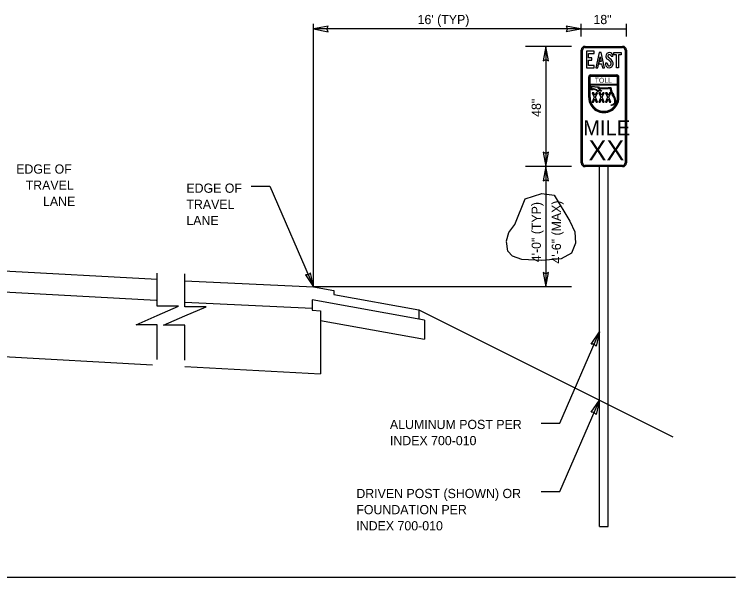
# Model space of a CAD drawing. Extents: x 56768 to 57406, y 11696 to 12105.
# Drawn here: x 57187.3 to 57405.9, y 11934.3 to 12105.2 of the extents above; entities that cross this region are included whole.
import ezdxf

# ---------------------------------------------------------------- set-up
doc = ezdxf.new("R2010")
doc.units = 0
for name, color, linetype in [('1', 7, 'Continuous'), ('52', 7, 'Continuous'), ('62', 7, 'Continuous'), ('Default', 7, 'Continuous'), ('DimLines_dp', 7, 'Continuous'), ('SheetBorder_dp', 7, 'Continuous'), ('SignPanel', 7, 'Continuous'), ('XSGrdLine_ex', 7, 'Continuous')]:
    doc.layers.add(name, color=color, linetype=linetype)

msp = doc.modelspace()

# ---------------------------------------------------------------- linework, layer by layer
at = {"layer": '1'}
for p, q in [((57364.62, 11988.09), (57364.62, 12058.97)), ((57367.28, 11986.75), (57367.28, 12058.97)), ((57364.62, 11949.76), (57364.62, 11988.09)), ((57367.28, 11949.76), (57367.28, 11986.75)), ((57364.62, 11949.76), (57367.28, 11949.76))]:
    msp.add_line(p, q, dxfattribs=at)
at = {"layer": '52'}
msp.add_line((57356.11, 12022.47), (57277.99, 12022.47), dxfattribs=at)
at = {"layer": '62'}
msp.add_lwpolyline([(57336.45, 12036.41), (57337.15, 12039.01), (57338.95, 12041.42), (57342.06, 12049.17), (57347.16, 12050.77), (57350.86, 12050.27), (57355.66, 12042.42), (57357.16, 12039.21), (57357.36, 12035.71), (57356.16, 12032.7), (57353.06, 12031), (57347.16, 12030.5), (57341.05, 12030.8), (57338.25, 12031.8), (57336.85, 12033.31), (57336.45, 12036.21)], dxfattribs=at)
at = {"layer": 'Default'}
for points in [[(57230.6, 12000.41), (57230.6, 12010.97), (57224.14, 12010.97), (57230.6, 12013.79), (57237.06, 12016.6), (57230.6, 12016.6), (57230.6, 12026.6)], [(57238.9, 12000.28), (57238.9, 12010.84), (57232.44, 12010.84), (57238.9, 12013.65), (57245.36, 12016.47), (57238.9, 12016.47), (57238.9, 12026.47)]]:
    msp.add_lwpolyline(points, dxfattribs=at)
at = {"layer": 'DimLines_dp'}
for p, q in [((57277.99, 12022.47), (57277.99, 12102.3)), ((57359.11, 12098.47), (57359.11, 12102.3)), ((57372.79, 12098.47), (57372.79, 12102.3)), ((57282.34, 12101.56), (57277.99, 12100.75)), ((57359.11, 12100.75), (57277.99, 12100.75)), ((57277.99, 12100.75), (57282.34, 12099.91)), ((57282.01, 12100.75), (57282.34, 12101.56)), ((57282.34, 12099.91), (57282.01, 12100.75)), ((57358.92, 12100.75), (57354.57, 12101.59)), ((57354.57, 12101.59), (57354.9, 12100.75)), ((57354.9, 12100.75), (57354.57, 12099.94)), ((57354.57, 12099.94), (57358.92, 12100.75)), ((57359.11, 12100.75), (57372.79, 12100.75)), ((57356.11, 12095.47), (57342.18, 12095.47)), ((57348.36, 12095.47), (57347.52, 12091.12)), ((57348.36, 12095.47), (57348.36, 12058.97)), ((57349.17, 12091.12), (57348.36, 12095.47)), ((57347.52, 12091.12), (57348.36, 12091.45)), ((57348.36, 12091.45), (57349.17, 12091.12)), ((57348.36, 12062.99), (57347.55, 12063.32)), ((57347.55, 12063.32), (57348.36, 12058.97)), ((57348.36, 12062.99), (57347.55, 12063.32)), ((57347.55, 12063.32), (57348.36, 12058.97)), ((57348.36, 12058.97), (57349.2, 12063.32)), ((57349.2, 12063.32), (57348.36, 12062.99)), ((57348.36, 12058.97), (57349.2, 12063.32)), ((57349.2, 12063.32), (57348.36, 12062.99)), ((57356.11, 12058.97), (57342.18, 12058.97)), ((57348.36, 12058.97), (57347.52, 12054.62)), ((57348.36, 12058.97), (57348.36, 12022.47)), ((57349.17, 12054.62), (57348.36, 12058.97)), ((57347.52, 12054.62), (57348.36, 12054.95)), ((57348.36, 12054.95), (57349.17, 12054.62)), ((57259.02, 12053.08), (57264.67, 12053.08)), ((57264.67, 12053.08), (57277.99, 12022.46)), ((57276.38, 12026.15), (57275.51, 12026.13)), ((57275.51, 12026.13), (57277.99, 12022.46)), ((57277.02, 12026.79), (57276.38, 12026.15)), ((57277.99, 12022.46), (57277.02, 12026.79)), ((57348.36, 12026.49), (57347.55, 12026.82)), ((57347.55, 12026.82), (57348.36, 12022.47)), ((57348.36, 12022.47), (57349.2, 12026.82)), ((57349.2, 12026.82), (57348.36, 12026.49)), ((57352.58, 11981.13), (57364.62, 12008.81)), ((57362.14, 12005.14), (57364.62, 12008.81)), ((57364.62, 12008.81), (57363.65, 12004.48)), ((57363.01, 12005.12), (57362.14, 12005.14)), ((57363.65, 12004.48), (57363.01, 12005.12)), ((57352.58, 11960.41), (57364.62, 11988.09)), ((57362.14, 11984.42), (57364.62, 11988.09)), ((57364.62, 11988.09), (57363.65, 11983.76)), ((57363.01, 11984.4), (57362.14, 11984.42)), ((57363.65, 11983.76), (57363.01, 11984.4)), ((57346.93, 11981.13), (57352.58, 11981.13)), ((57346.93, 11960.41), (57352.58, 11960.41))]:
    msp.add_line(p, q, dxfattribs=at)
at = {"layer": 'SheetBorder_dp'}
msp.add_line((57405.89, 11934.25), (56789.89, 11934.25), dxfattribs=at)
at = {"layer": 'SignPanel'}
for p, q in [((57368.14, 12092.46), (57368.73, 12092.46)), ((57368.14, 12092.46), (57368.73, 12092.46)), ((57368.14, 12092.46), (57368.73, 12092.46)), ((57367.01, 12090.42), (57366.41, 12090.42)), ((57367.01, 12090.42), (57366.41, 12090.42)), ((57367.01, 12090.42), (57366.41, 12090.42)), ((57361.96, 12086.8), (57369.94, 12086.8)), ((57361.39, 12079.95), (57361.39, 12086.23)), ((57361.58, 12079.95), (57361.58, 12086.23)), ((57361.77, 12083.95), (57361.77, 12086.23)), ((57361.96, 12086.61), (57369.94, 12086.61)), ((57361.96, 12086.42), (57369.94, 12086.42)), ((57370.13, 12083.95), (57370.13, 12086.23)), ((57370.32, 12079.95), (57370.32, 12086.23)), ((57370.51, 12079.95), (57370.51, 12086.23)), ((57361.77, 12083.95), (57370.13, 12083.95)), ((57361.77, 12079.95), (57361.77, 12083.76)), ((57361.77, 12083.76), (57370.13, 12083.76)), ((57362.15, 12082.3), (57361.98, 12083.39)), ((57361.98, 12083.39), (57364.36, 12083.21)), ((57364.2, 12082.99), (57362.25, 12083.14)), ((57362.25, 12083.14), (57362.35, 12082.51)), ((57362.35, 12082.51), (57362.54, 12082.48)), ((57362.54, 12082.48), (57362.81, 12082.7)), ((57362.86, 12082.44), (57362.61, 12082.24)), ((57362.81, 12082.7), (57363.73, 12082.4)), ((57363.61, 12082.19), (57362.86, 12082.44)), ((57363.24, 12083.05), (57363.24, 12083.05)), ((57363.73, 12082.4), (57364.18, 12081.98)), ((57364.34, 12082.63), (57364.2, 12082.99)), ((57367.35, 12082.63), (57364.34, 12082.63)), ((57364.36, 12083.21), (57364.5, 12082.86)), ((57364.5, 12082.86), (57367.23, 12082.86)), ((57367.23, 12082.86), (57367.33, 12083.02)), ((57367.33, 12083.02), (57368.06, 12083.02)), ((57367.45, 12082.79), (57367.35, 12082.63)), ((57367.88, 12082.79), (57367.45, 12082.79)), ((57368.18, 12081.5), (57367.88, 12082.79)), ((57368.06, 12083.02), (57368.4, 12081.58)), ((57370.13, 12079.95), (57370.13, 12083.76)), ((57362.61, 12082.24), (57362.15, 12082.3)), ((57364.15, 12081.7), (57363.61, 12082.19)), ((57364.78, 12082.07), (57364.15, 12081.7)), ((57364.18, 12081.98), (57364.79, 12082.34)), ((57365.16, 12081.81), (57364.78, 12082.07)), ((57364.79, 12082.34), (57365.29, 12082)), ((57365.29, 12082), (57365.16, 12081.81)), ((57368.62, 12080.79), (57368.18, 12081.5)), ((57368.4, 12081.58), (57368.85, 12080.86)), ((57368.62, 12080.61), (57368.62, 12080.79)), ((57369.05, 12079.91), (57368.62, 12080.61)), ((57368.85, 12080.86), (57368.85, 12080.67)), ((57368.85, 12080.67), (57369.26, 12080)), ((57368.65, 12077.81), (57369.28, 12078.32)), ((57369.51, 12078.21), (57368.76, 12077.6)), ((57369.28, 12079.05), (57369.05, 12079.91)), ((57369.26, 12080), (57369.51, 12079.08)), ((57369.28, 12078.32), (57369.28, 12079.05)), ((57369.51, 12079.08), (57369.51, 12078.21)), ((57368.18, 12077.67), (57368.31, 12077.86)), ((57368.4, 12077.51), (57368.18, 12077.67)), ((57368.31, 12077.86), (57368.45, 12077.76)), ((57368.76, 12077.6), (57368.4, 12077.51)), ((57368.45, 12077.76), (57368.65, 12077.81))]:
    msp.add_line(p, q, dxfattribs=at)
for points in [[(57360.25, 12095.47), (57371.65, 12095.47)], [(57359.11, 12060.11), (57359.11, 12094.33)], [(57359.49, 12060.11), (57359.49, 12094.33)], [(57360.25, 12095.09), (57371.65, 12095.09)], [(57372.41, 12094.33), (57372.41, 12060.11)], [(57372.79, 12094.33), (57372.79, 12060.11)], [(57371.65, 12059.35), (57360.25, 12059.35)], [(57371.65, 12058.97), (57360.25, 12058.97)]]:
    msp.add_lwpolyline(points, dxfattribs=at)
for points in [[(57361.31, 12089.69), (57361.31, 12091.31), (57362.33, 12091.31), (57362.33, 12092.02), (57361.31, 12092.02), (57361.31, 12093.34), (57363.03, 12093.34), (57363.03, 12094.05), (57360.66, 12094.05), (57360.66, 12088.98), (57363.03, 12088.98), (57363.03, 12089.69)], [(57361.31, 12089.69), (57361.31, 12091.31), (57362.33, 12091.31), (57362.33, 12092.02), (57361.31, 12092.02), (57361.31, 12093.34), (57363.03, 12093.34), (57363.03, 12094.05), (57360.66, 12094.05), (57360.66, 12088.98), (57363.03, 12088.98), (57363.03, 12089.69)], [(57361.31, 12089.69), (57361.31, 12091.31), (57362.33, 12091.31), (57362.33, 12092.02), (57361.31, 12092.02), (57361.31, 12093.34), (57363.03, 12093.34), (57363.03, 12094.05), (57360.66, 12094.05), (57360.66, 12088.98), (57363.03, 12088.98), (57363.03, 12089.69)], [(57365.28, 12090.21), (57365.55, 12088.98), (57366.16, 12088.98), (57365.14, 12093.56), (57364.51, 12093.56), (57363.49, 12088.98), (57364.09, 12088.98), (57364.37, 12090.21)], [(57364.51, 12090.85), (57364.37, 12090.21), (57365.28, 12090.21), (57365.55, 12088.98), (57366.16, 12088.98), (57365.14, 12093.56), (57364.51, 12093.56), (57363.49, 12088.98), (57364.09, 12088.98), (57364.82, 12092.26), (57365.14, 12090.85)], [(57364.51, 12090.85), (57364.37, 12090.21), (57365.28, 12090.21), (57365.55, 12088.98), (57366.16, 12088.98), (57365.14, 12093.56), (57364.51, 12093.56), (57363.49, 12088.98), (57364.09, 12088.98), (57364.82, 12092.26), (57365.14, 12090.85)], [(57369.79, 12092.92), (57369.01, 12092.92), (57369.01, 12093.56), (57371.16, 12093.56), (57371.16, 12092.92), (57370.38, 12092.92), (57370.38, 12088.98), (57369.79, 12088.98)], [(57369.79, 12092.92), (57369.01, 12092.92), (57369.01, 12093.56), (57371.16, 12093.56), (57371.16, 12092.92), (57370.38, 12092.92), (57370.38, 12088.98), (57369.79, 12088.98)], [(57369.79, 12092.92), (57369.01, 12092.92), (57369.01, 12093.56), (57371.16, 12093.56), (57371.16, 12092.92), (57370.38, 12092.92), (57370.38, 12088.98), (57369.79, 12088.98)], [(57364.82, 12092.26), (57365.14, 12090.85), (57364.51, 12090.85)], [(57362.84, 12078.53), (57363.25, 12079.51), (57363.66, 12078.53), (57364.08, 12078.53), (57363.46, 12080.02), (57364.03, 12081.39), (57363.61, 12081.39), (57363.25, 12080.53), (57362.89, 12081.39), (57362.46, 12081.39), (57363.03, 12080.02), (57362.41, 12078.53)], [(57364.86, 12078.53), (57365.26, 12079.51), (57365.67, 12078.53), (57366.1, 12078.53), (57365.48, 12080.02), (57366.05, 12081.39), (57365.62, 12081.39), (57365.26, 12080.53), (57364.91, 12081.39), (57364.48, 12081.39), (57365.05, 12080.02), (57364.43, 12078.53)], [(57366.87, 12078.53), (57367.28, 12079.51), (57367.69, 12078.53), (57368.12, 12078.53), (57367.49, 12080.02), (57368.07, 12081.39), (57367.64, 12081.39), (57367.28, 12080.53), (57366.92, 12081.39), (57366.49, 12081.39), (57367.07, 12080.02), (57366.44, 12078.53)]]:
    msp.add_lwpolyline(points, close=True, dxfattribs=at)
for centre, radius, start, end in [((57360.25, 12094.33), 1.14, 90, 180), ((57371.65, 12094.33), 1.14, 0, 90), ((57360.25, 12094.33), 0.76, 90, 180), ((57371.65, 12094.33), 0.76, 0, 90), ((57360.25, 12060.11), 1.14, 180, 270), ((57360.25, 12060.11), 0.76, 180, 270), ((57371.65, 12060.11), 1.14, 270, 360), ((57371.65, 12060.11), 0.76, 270, 360)]:
    msp.add_arc(centre, radius, start, end, dxfattribs=at)
for centre, major_axis, ratio, start_param, end_param in [((57367.64, 12092.43), (0, 1.19), 0.91923, 4.736267, 7.790596), ((57367.64, 12092.43), (0, 1.19), 0.91923, 4.736267, 7.790596), ((57367.64, 12092.43), (0, 1.19), 0.91923, 4.736267, 7.790596), ((57367.53, 12092.47), (0, 1.07), 0.91923, 1.534831, 2.511766), ((57367.53, 12092.47), (0, 1.07), 0.91923, 1.534831, 2.511766), ((57367.53, 12092.47), (0, 1.07), 0.91923, 1.534831, 2.511766), ((57364.92, 12087.53), (0, 4.63), 0.91923, 5.515137, 5.786988), ((57364.92, 12087.53), (0, 4.63), 0.91923, 5.515137, 5.786988), ((57364.92, 12087.53), (0, 4.63), 0.91923, 5.515137, 5.786988), ((57367.57, 12092.49), (0, 0.46), 0.91923, 0.87378, 2.656959), ((57367.57, 12092.49), (0, 0.46), 0.91923, 0.87378, 2.656959), ((57367.57, 12092.49), (0, 0.46), 0.91923, 0.87378, 2.656959), ((57367.63, 12092.42), (0, 0.558), 0.91923, 4.786904, 7.140738), ((57367.63, 12092.42), (0, 0.558), 0.91923, 4.786904, 7.140738), ((57367.63, 12092.42), (0, 0.558), 0.91923, 4.786904, 7.140738), ((57365.43, 12088.23), (0, 4.39), 0.91923, 5.462886, 5.782242), ((57365.43, 12088.23), (0, 4.39), 0.91923, 5.462886, 5.782242), ((57365.43, 12088.23), (0, 4.39), 0.91923, 5.462886, 5.782242), ((57367.45, 12090.23), (0, 1.42), 0.91923, 4.260987, 5.485755), ((57367.45, 12090.23), (0, 1.42), 0.91923, 4.260987, 5.485755), ((57367.45, 12090.23), (0, 1.42), 0.91923, 4.260987, 5.485755), ((57367.79, 12090.35), (0, 1.5), 0.91923, 1.526364, 2.701682), ((57367.79, 12090.35), (0, 1.5), 0.91923, 1.526364, 2.701682), ((57367.79, 12090.35), (0, 1.5), 0.91923, 1.526364, 2.701682), ((57367.84, 12090.38), (0, 0.911), 0.91923, 1.524757, 2.28214), ((57367.84, 12090.38), (0, 0.911), 0.91923, 1.524757, 2.28214), ((57367.84, 12090.38), (0, 0.911), 0.91923, 1.524757, 2.28214), ((57367.6, 12090.17), (0, 1.24), 0.91923, 2.786047, 4.251692), ((57367.6, 12090.17), (0, 1.24), 0.91923, 2.786047, 4.251692), ((57367.6, 12090.17), (0, 1.24), 0.91923, 2.786047, 4.251692), ((57367.62, 12090.15), (0, 0.581), 0.91923, 2.261787, 4.23006), ((57367.62, 12090.15), (0, 0.581), 0.91923, 2.261787, 4.23006), ((57367.62, 12090.15), (0, 0.581), 0.91923, 2.261787, 4.23006), ((57367.44, 12090.23), (0, 0.792), 0.91923, 4.254409, 5.632398), ((57367.44, 12090.23), (0, 0.792), 0.91923, 4.254409, 5.632398), ((57367.44, 12090.23), (0, 0.792), 0.91923, 4.254409, 5.632398), ((57361.96, 12086.23), (0, 0.57), 0.9997, 0, 1.570796), ((57369.94, 12086.23), (0, 0.57), 0.9997, 4.712389, 6.283185), ((57361.96, 12086.23), (0, 0.38), 0.9997, 0, 1.570796), ((57361.96, 12086.23), (0, 0.19), 0.9997, 0, 1.570796), ((57369.94, 12086.23), (0, 0.38), 0.9997, 4.712389, 6.283185), ((57369.94, 12086.23), (0, 0.19), 0.9997, 4.712389, 6.283185), ((57365.95, 12079.95), (0, -4.56), 0.9997, 4.712389, 7.853982), ((57365.95, 12079.95), (0, -4.37), 0.9997, 4.712389, 7.853982), ((57365.95, 12079.95), (0, -4.18), 0.9997, 4.712389, 7.853982)]:
    msp.add_ellipse(centre, major_axis=major_axis, ratio=ratio, start_param=start_param, end_param=end_param, dxfattribs=at)
at = {"layer": 'XSGrdLine_ex'}
for p, q in [((57167.72, 12028.26), (57230.6, 12024.78)), ((57230.24, 12018.3), (57168, 12021.75)), ((57277.99, 12022.46), (57284.15, 12021.36)), ((57284.15, 12021.36), (57284.15, 12020.18)), ((57284.15, 12020.18), (57309.87, 12015.55)), ((57277.57, 12018.53), (57277.57, 12015.37)), ((57311.57, 12012.41), (57277.57, 12018.53)), ((57277.57, 12015.37), (57280.04, 12015.22)), ((57280.04, 12015.22), (57280.04, 11996.05)), ((57309.87, 12015.55), (57309.87, 12012.71)), ((57311.57, 12012.41), (57311.57, 12006.59)), ((57280.04, 12012.26), (57311.57, 12006.59)), ((57167.12, 12002.3), (57229.16, 11998.86)), ((57238.9, 11998.32), (57280.04, 11996.05))]:
    msp.add_line(p, q, dxfattribs=at)
for points in [[(57238.9, 12024.32), (57277.99, 12022.46)], [(57238.9, 12017.82), (57277.57, 12015.99)], [(57309.87, 12015.55), (57386.82, 11976.95)]]:
    msp.add_lwpolyline(points, dxfattribs=at)

# ---------------------------------------------------------------- texts
at = {"layer": 'DimLines_dp'}
for s, p in [("16' (TYP)", (57309.5, 12102.22)), ('18"', (57362.81, 12102.22)), ('EDGE OF ', (57187.82, 12056.84)), ('TRAVEL ', (57190.69, 12051.94)), ('EDGE OF ', (57239.41, 12051.04)), ('LANE', (57195.95, 12047.04)), ('TRAVEL ', (57239.41, 12046.14)), ('LANE', (57239.41, 12041.24)), ('ALUMINUM POST PER', (57301.11, 11979.33)), ('INDEX 700-010', (57301.11, 11974.43)), ('DRIVEN POST (SHOWN) OR', (57290.93, 11958.38)), ('FOUNDATION PER', (57290.93, 11953.48)), ('INDEX 700-010', (57290.93, 11948.58))]:
    msp.add_text(s, height=2.8, dxfattribs=at).set_placement(p)
for s, p in [('48"', (57346.87, 12074.08)), ('4\'-0" (TYP)', (57346.87, 12029.97)), ('4\'-6" (MAX)', (57352.95, 12029.57))]:
    msp.add_text(s, height=2.8, rotation=90, dxfattribs=at).set_placement(p)
at = {"layer": 'SignPanel'}
for s, height, p in [('TOLL', 1.519, (57363.19, 12084.42)), ('MILE', 4.562, (57359.7, 12068.47)), ('XX', 6.083, (57361.31, 12060.9))]:
    msp.add_text(s, height=height, dxfattribs=at).set_placement(p)

doc.saveas('drawing.dxf')
